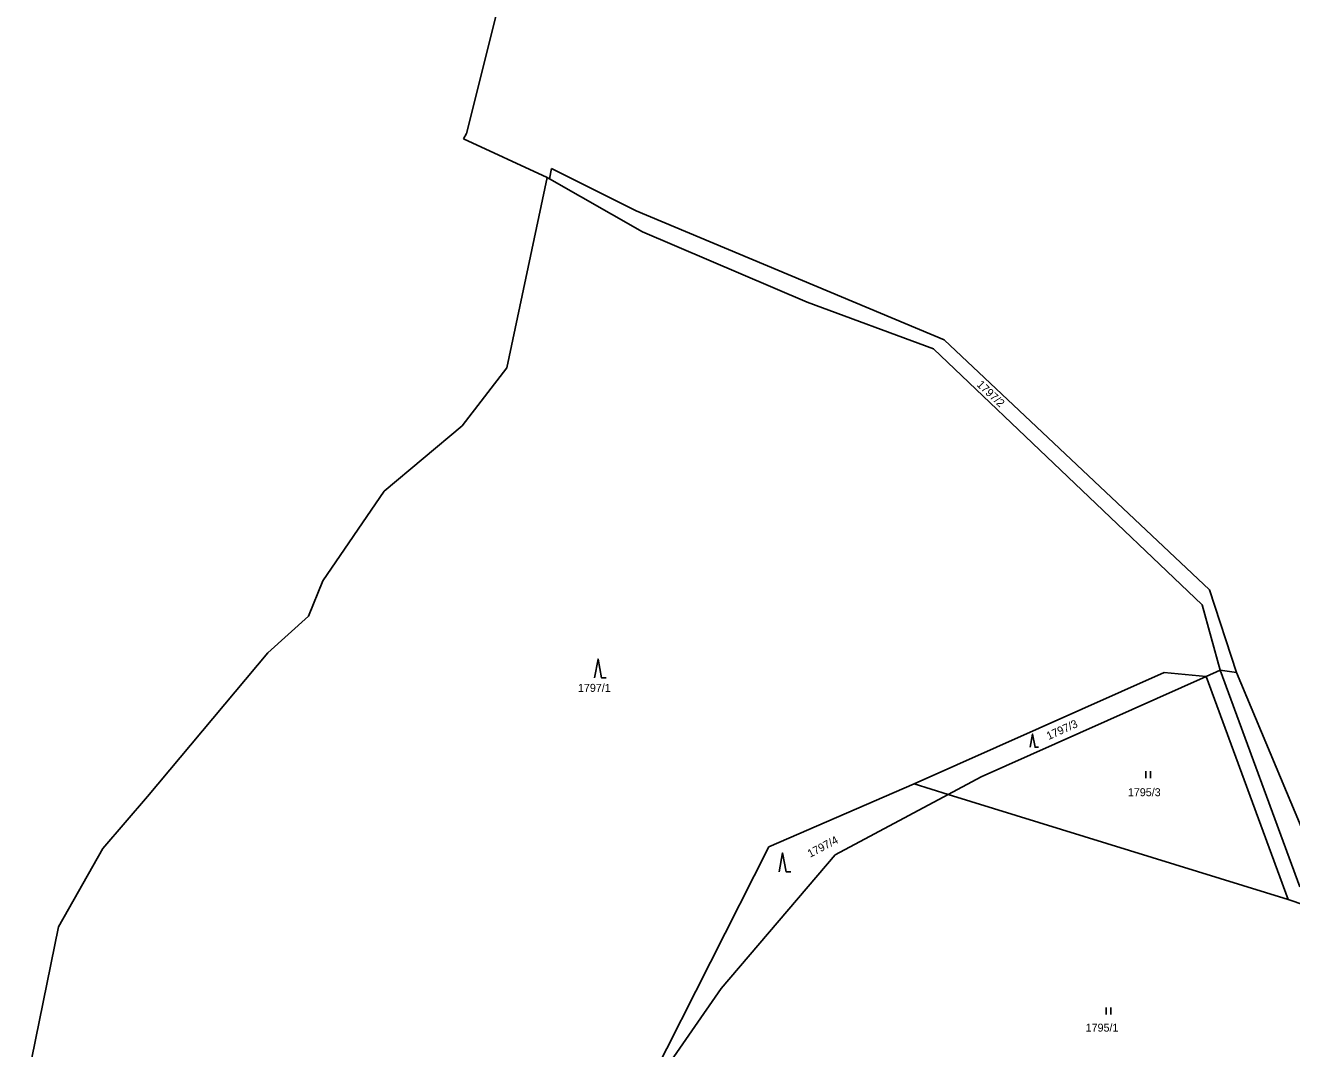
# Model space of a CAD drawing. Extents: x -609861 to -605046, y -1120287 to -1116307.
# Drawn here: x -609225.9 to -608956.9, y -1117720.7 to -1117503.3 of the extents above; entities that cross this region are included whole.
import ezdxf

# ---------------------------------------------------------------- set-up
doc = ezdxf.new("R2010")
doc.units = 0
for name, color, linetype in [('Vrstva 1', 7, 'Continuous'), ('Vrstva 2', 7, 'Continuous'), ('Vrstva 3', 7, 'Continuous')]:
    doc.layers.add(name, color=color, linetype=linetype)

msp = doc.modelspace()

# ---------------------------------------------------------------- linework, layer by layer
at = {"layer": 'Vrstva 1'}
for p, q in [((-609132.18, -1117526.21), (-609125.44, -1117499.39)), ((-609132.79, -1117527.35), (-609132.18, -1117526.21)), ((-609115.01, -1117535.58), (-609132.79, -1117527.35)), ((-609123.6, -1117576.02), (-609115.01, -1117535.58)), ((-609115.01, -1117535.58), (-609114.53, -1117535.86)), ((-609114.53, -1117535.86), (-609114.08, -1117533.7)), ((-609114.53, -1117535.86), (-609094.81, -1117547.16)), ((-609114.08, -1117533.7), (-609096.13, -1117542.69)), ((-609096.13, -1117542.69), (-609030.73, -1117570.09)), ((-609094.81, -1117547.16), (-609059.82, -1117562.06)), ((-609059.82, -1117562.06), (-609032.99, -1117571.99)), ((-609030.73, -1117570.09), (-608974.34, -1117623.19)), ((-609032.99, -1117571.99), (-608975.9, -1117626.43)), ((-609133.1, -1117588.37), (-609123.6, -1117576.02)), ((-609149.66, -1117602.27), (-609133.1, -1117588.37)), ((-609162.69, -1117621.29), (-609149.66, -1117602.27)), ((-609165.76, -1117628.81), (-609162.69, -1117621.29)), ((-608974.34, -1117623.19), (-608968.58, -1117640.77)), ((-608975.9, -1117626.43), (-608972.04, -1117640.31)), ((-609174.34, -1117636.61), (-609165.76, -1117628.81)), ((-609199.95, -1117667.12), (-609174.34, -1117636.61)), ((-609037.06, -1117664.46), (-608983.96, -1117640.81)), ((-608983.96, -1117640.81), (-608975.04, -1117641.64)), ((-608975.04, -1117641.64), (-608972.04, -1117640.31)), ((-608972.04, -1117640.31), (-608955.13, -1117686.31)), ((-608968.58, -1117640.77), (-608972.04, -1117640.31)), ((-608968.58, -1117640.77), (-608950.85, -1117683.2)), ((-609022.87, -1117662.93), (-608975.04, -1117641.64)), ((-608975.04, -1117641.64), (-608957.65, -1117689)), ((-609067.96, -1117677.82), (-609037.06, -1117664.46)), ((-609029.88, -1117666.68), (-609037.06, -1117664.46)), ((-609029.88, -1117666.68), (-609022.87, -1117662.93)), ((-609209.45, -1117678.19), (-609199.95, -1117667.12)), ((-609053.84, -1117679.49), (-609029.88, -1117666.68)), ((-608957.65, -1117689), (-609029.88, -1117666.68)), ((-609218.81, -1117694.79), (-609209.45, -1117678.19)), ((-609096.9, -1117735.12), (-609067.96, -1117677.82)), ((-609078.06, -1117707.9), (-609053.84, -1117679.49)), ((-608957.65, -1117689), (-608916.44, -1117702.91)), ((-609225.88, -1117729.4), (-609218.81, -1117694.79)), ((-609096.9, -1117735.12), (-609078.06, -1117707.9))]:
    msp.add_line(p, q, dxfattribs=at)
at = {"layer": 'Vrstva 3'}
for p, q in [((-608987.86, -1117661.75), (-608987.86, -1117663.25)), ((-608986.86, -1117663.25), (-608986.86, -1117661.75)), ((-608996.26, -1117711.98), (-608996.26, -1117713.48)), ((-608995.26, -1117713.48), (-608995.26, -1117711.98))]:
    msp.add_line(p, q, dxfattribs=at)
for points in [[(-609104.98, -1117641.94), (-609104.23, -1117637.94), (-609103.48, -1117641.94), (-609102.48, -1117641.94)], [(-609012.425, -1117656.66), (-609011.9, -1117653.86), (-609011.375, -1117656.66), (-609010.675, -1117656.66)], [(-609065.77, -1117683.1), (-609065.02, -1117679.1), (-609064.27, -1117683.1), (-609063.27, -1117683.1)]]:
    msp.add_lwpolyline(points, dxfattribs=at)

# ---------------------------------------------------------------- texts
at = {"layer": 'Vrstva 2'}
for s, rotation, p in [('1797/2', 316.78836, (-609023.904, -1117579.769)), ('1797/3', 24.29341, (-609008.502, -1117655.138)), ('1797/4', 27.90304, (-609059.173, -1117680.156))]:
    msp.add_text(s, height=1.7, rotation=rotation, dxfattribs=at).set_placement(p)
for s, p in [('1797/1', (-609108.487, -1117644.89)), ('1795/3', (-608991.667, -1117667.07)), ('1795/1', (-609000.637, -1117717.09))]:
    msp.add_text(s, height=1.7, dxfattribs=at).set_placement(p)

doc.saveas('drawing.dxf')
